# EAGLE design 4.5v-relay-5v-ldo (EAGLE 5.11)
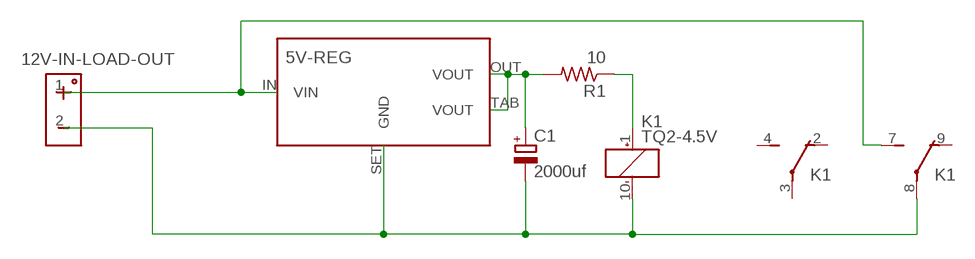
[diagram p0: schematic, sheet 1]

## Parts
5V-REG  REG1117  [SOT-223-3]
12V-IN-LOAD-OUT  HEADER-POWER  [HEADER-POWER-PTH]
C1  2000uf  CPOL-EUE3.5-10  [E3,5-10]
K1  TQ2-4.5V  [TQ2]
R1  10  R-US_0617/22  [0617/22]

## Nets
N$2: 5V-REG.IN(VIN) 12V-IN-LOAD-OUT.1 K1.7(2:S)
N$3: K1.1(_:+) R1.1
N$4: 5V-REG.OUT(VOUT) 5V-REG.TAB(VOUT) C1.+ R1.2
N$5: 5V-REG.SET(GND) 12V-IN-LOAD-OUT.2 C1.- K1.8(2:P) K1.10(_:-)
Unconnected: K1.2(1:O) K1.3(1:P) K1.4(1:S) K1.9(2:O)

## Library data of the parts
5V-REG = trl:REG1117
12V-IN-LOAD-OUT = trl:HEADER-POWER
C1 = rcl:CPOL-EU: POLARIZED CAPACITOR, European symbol
K1 = relay:TQ2?*: LOW PROFILE 2 FORM C RELAY NAiS Source: http://www.mew-europe.com/.. en_ds_61020_0001.pdf Source: http://www.mew-europe.com/.. en_ds_61020_0004.pdf; MF: AROMAT/ MATSUSHITA; MPN: TQ2-4.5V; OC_FARNELL: 1163566; OC_NEWARK: 64K3199
R1 = resistor:R-US_: RESISTOR, American symbol

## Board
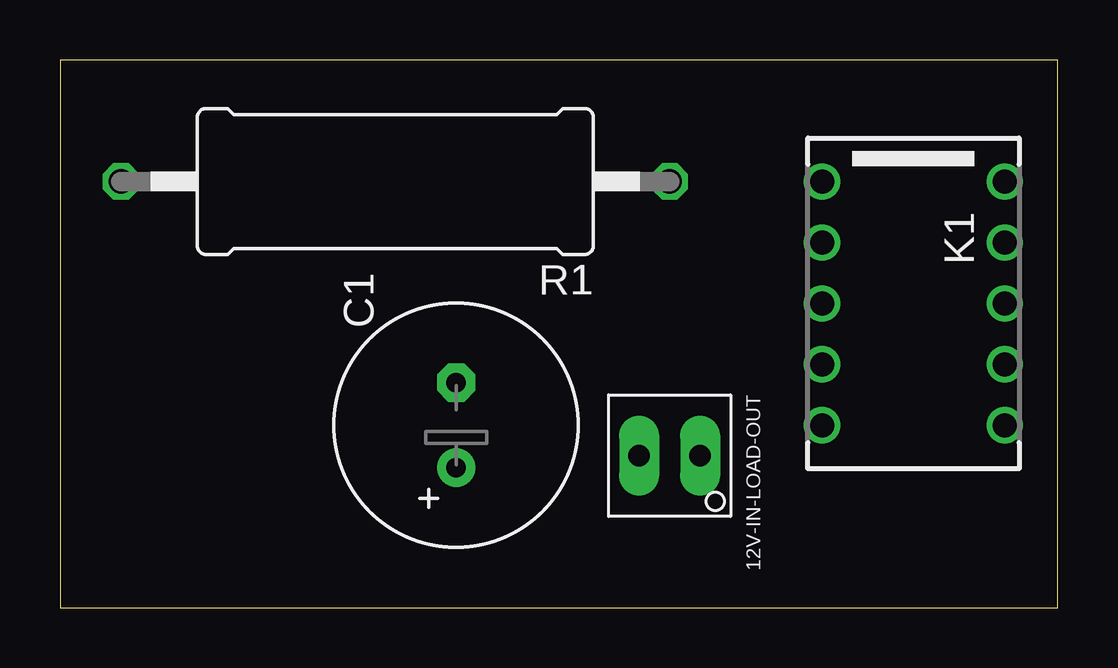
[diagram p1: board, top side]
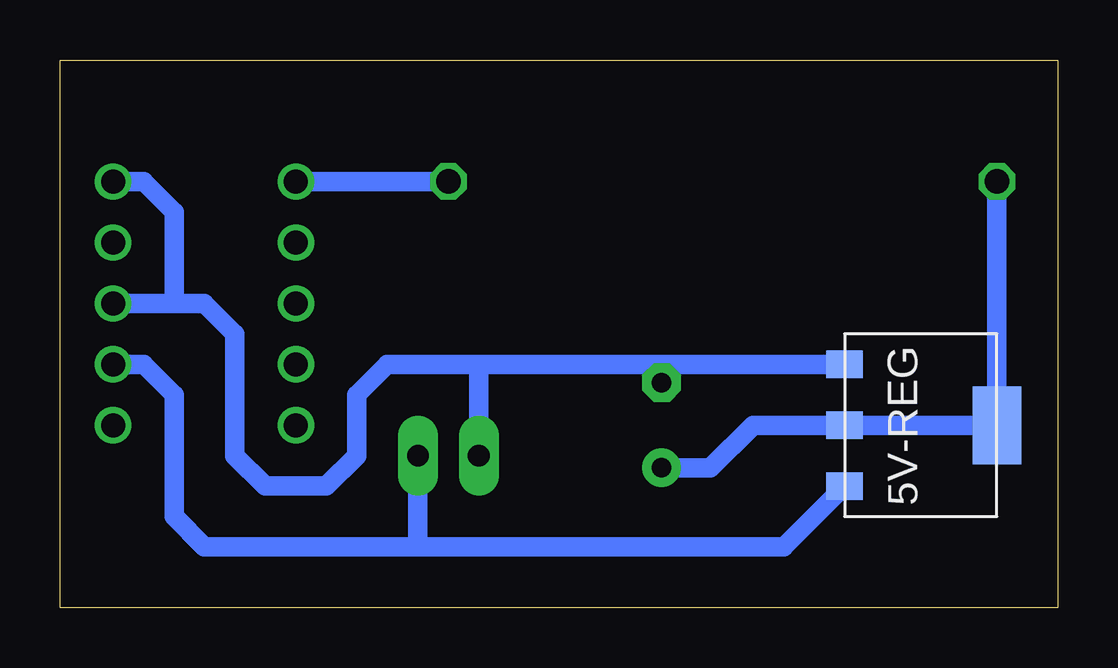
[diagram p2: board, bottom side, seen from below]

Size 41.58 x 22.85 mm. Coordinates in mm from the lower left corner, seen from the top.
Outline: 0,0 41.58,0 41.58,22.85 0,22.85 0,0
Copper layers (1*16): Top 0.035mm / dielectric 1.5mm / Bottom 0.035mm
Design rules "default": minimum track width 10mil, minimum drill 0.6mm, track to track 8mil, track to pad 8mil, pad to pad 8mil, via to via 8mil, smd to smd 8mil, copper to edge 40mil, drill to drill 8mil, minimum pad ring 10mil, minimum via ring 8mil, stop-mask expansion 4mil, vias tented up to drill 0mil, thermal gap 10mil

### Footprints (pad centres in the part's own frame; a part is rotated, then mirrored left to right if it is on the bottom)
SOT-223-3 = smd 1.143 x 1.524: IN 5.08,0; OUT 2.54,0; SET 0,0 | smd 3.251 x 2.032: TAB 2.54,6.35
HEADER-POWER-PTH = drill 0.9 pad 1.676 long: 1 0,1.27; 2 0,-1.27
E3,5-10 = drill 0.813 pad 1.6 round: + -1.778,0 | drill 0.813 pad 1.6 octagon: - 1.778,0
TQ2 = drill 1 round: 1 -5.08,-3.81; 2 -2.54,-3.81; 3 0,-3.81; 4 2.54,-3.81; 5 5.08,-3.81; 6 5.08,3.81; 7 2.54,3.81; 8 0,3.81; 9 -2.54,3.81; 10 -5.08,3.81
0617/22 = drill 1.016 octagon: 1 -11.43,0; 2 11.43,0

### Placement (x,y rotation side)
5V-REG  8.89,10.16 270 bottom
12V-IN-LOAD-OUT  25.4,6.35 270 top
C1  16.51,7.62 90 top
K1  35.56,12.7 270 top
R1  13.97,17.78 180 top

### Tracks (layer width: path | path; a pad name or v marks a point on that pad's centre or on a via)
N$2
  Bottom 0.813: 5V-REG.IN 11.43,2.54 26.67,2.54 | 26.67,2.54 35.56,2.54 36.83,3.81 36.83,8.89 38.1,10.16 K1.7 | 26.67,2.54 12V-IN-LOAD-OUT.1
N$3
  Bottom 0.813: R1.1 K1.1
N$4
  Bottom 0.813: C1.+ 14.48,5.84 12.7,7.62 5V-REG.OUT 5V-REG.TAB R1.2
N$5
  Bottom 0.813: 5V-REG.SET 16.51,10.16 | 16.51,10.16 24.13,10.16 | 24.13,10.16 27.94,10.16 29.21,8.89 29.21,6.35 30.48,5.08 33.02,5.08 34.29,6.35 34.29,11.43 35.56,12.7 36.83,12.7 | 36.83,12.7 K1.8 | K1.10 38.1,17.78 36.83,16.51 36.83,12.7 | 24.13,10.16 12V-IN-LOAD-OUT.2 | 16.51,10.16 C1.-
